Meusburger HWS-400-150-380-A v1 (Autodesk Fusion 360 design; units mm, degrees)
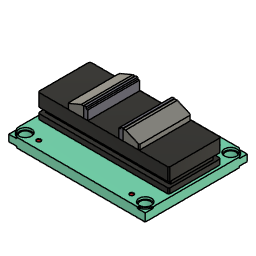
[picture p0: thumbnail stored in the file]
parameter "Ouverture" = 100
base_feature "Base Feature1" OffsetX 0 OffsetY 0 OffsetZ 0 OffsetX 0 OffsetY 0 OffsetZ 0 OffsetX 0 OffsetY 0 OffsetZ 0
base_feature "Base Feature1"
base_feature "Base Feature1" OffsetX 0 OffsetY 0 OffsetZ 0
base_feature "Base Feature1"
base_feature "Base Feature1" OffsetX 0 OffsetY 0 OffsetZ 0 OffsetX 0 OffsetY 0 OffsetZ 0
as_built_joint "As-built1"
as_built_joint "As-built1"
joint "Assemble1" alignOffsetX 0 alignOffsetY 0 alignOffsetZ 45 (= "Ouverture / 2 - 5 mm")
joint "Assemble2" alignOffsetX 0 alignOffsetY 0 alignOffsetZ -45 (= "-Ouverture / 2 + 5 mm")
base_feature "Base Feature1"
position "Position1"
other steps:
create_component "CreateComponent1"
create_component "CreateComponent2"
create_component "CreateComponent1"
create_component "CreateComponent2"
create_component "CreateComponent3"
create_component "CreateComponent1"
create_component "CreateComponent2"
joint_origin "JointOrigin2" OffsetX 0 OffsetY 0 OffsetZ 0
joint_origin "JointOrigin4" OffsetX 0 OffsetY 0 OffsetZ 0
joint_origin "JointOrigin3" OffsetX 0 OffsetY 0 OffsetZ 0
joint_origin "JointOrigin5" OffsetX 0 OffsetY 0 OffsetZ 0
create_component "CreateComponent4"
